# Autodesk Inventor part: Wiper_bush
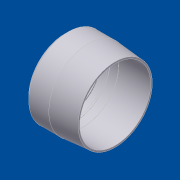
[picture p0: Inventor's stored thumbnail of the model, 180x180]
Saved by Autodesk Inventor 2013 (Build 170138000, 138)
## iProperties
Shininess: 50.0
Length Units: 11269
Angle Units: 11279
Time Units: 11290
Mass Units: 11283
Length Display Precision: 3
Angle Display Precision: 2
Created: 2001-04
Part Number: Wiper_bush
Material: Aluminium - 6061
Document SubType Name: Modellieren
Designer: dl
Density: 2.71 g/cm^3
Density: 2.71
Volumn: 8.111435151936158
Area: 89.07253648313032
PropertySet Name: Model Information
Control State: 0
Master: False
Checked Out: False
Author: dl
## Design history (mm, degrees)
body "Solid1"
revolve "Revolution1" stored, may be unused: angle "d4" = 90 deg
revolve "Revolution2" stored, may be unused: angle "d15" = 90 deg
chamfer "Chamfer1" distance "d17" = 2; stored, may be unused: second distance "d18" = 2, angle "d19" = 45 deg
sketch "Sketch1"
  geometry: L1 (0, 0)-(0, 23.5); L2 (0, 23.5)-(14, 23.5); L3 (14, 23.5)-(30, 22.1); L4 (30, 22.1)-(30, 0); L5 (30, 0)-(0, 0)
  constraints: 10 end point, 2 parallel, 1 perpendicular, 1 vertical
  dimensions: "Nennmaß" = 22.1 distance of L3.end L4.end; "d1" = 23.5 distance of L1.start L1.end; "d2" = 16 horizontal distance of L2.end L3.end; "d3" = 30 distance of L4.end L1.start
sketch "Sketch2"
  geometry: L1 (0, 0)-(0, 20.8); L2 (0, 20.8)-(-1, 20.8); L3 (-1, 20.8)-(-1, 21.5); L4 (-1, 21.5)-(-5, 21.5); L5 (-5, 21.5)-(-5, 20.8); L6 (-5, 20.8)-(-6, 20.8); L7 (-6, 20.8)-(-6, 21); L8 (-11, 21.1)-(-30, 21.1); L9 (-30, 21.1)-(-30, 0); L10 (-30, 0)-(0, 0); L11 (-6, 21)-(-11, 21); L12 (-11, 21)-(-11, 21.1); L13 (-30, 22.1)-(-30, -22.1) reference; L14 (0, 23.5)-(0, -23.5) reference; L15 (-30, 0)-(17.182, 0); L16 (-30, 0)-(25.595, 0)
  constraints: 28 end point, 8 parallel, 3 collinear, 3 perpendicular, 1 midpoint, 1 vertical
  dimensions: "d5" = 20.8 distance of L1.start L1.end; "d6" = 21.5 vertical distance of L1.start L3.end; "d7" = 21 distance between parallel lines of L10 L11; "d8" = 21.1 distance of L8.end L9.end; "d9" = 4 distance of L3.end L4.end; "d10" = 5 distance from line of L5.end L1; "d11" = 0 distance between parallel lines of L13 L9; "d12" = 19 distance of L8.start L8.end; "d13" = 24 distance from line of L7.end L9; "d14" = 0 distance between parallel lines of L14 L1; "d16" = 0 distance between parallel lines of L10 L16
